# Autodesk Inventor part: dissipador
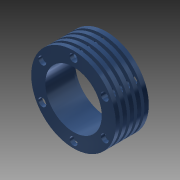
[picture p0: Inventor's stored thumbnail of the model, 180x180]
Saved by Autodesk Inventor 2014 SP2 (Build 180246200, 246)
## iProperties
Created: 2016-04
Part Number: dissipador
Material: Genérico
Document SubType Name: Modeling
Designer: Celiberto
Density: 1 g/cm^3
Appearance: Acetinada manchada - Azul
Mass: 2.14832 g
Surface Area: 38.898 cm^2
Volume: 2.14832 cm^3
Author: Celiberto
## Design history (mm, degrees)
sketch "Esboço1" dims "d10" = 10
  geometry: L1 (0, 0)-(16.385, 0); L2 (0, 0)-(0, 13.5); L3 (10.5, 13.5)-(10.5, 0); L4 (1.275, 13.5)-(1.275, 10.5); L5 (1.275, 10.5)-(2.275, 10.5); L6 (2.275, 10.5)-(2.275, 13.5); L7 (0, 13.5)-(1.275, 13.5); L8 (3.55, 13.5)-(3.55, 10.5); L9 (3.55, 10.5)-(4.55, 10.5); L10 (4.55, 10.5)-(4.55, 13.5); L11 (5.825, 13.5)-(5.825, 10.5); L12 (5.825, 10.5)-(6.825, 10.5); L13 (6.825, 10.5)-(6.825, 13.5); L14 (8.1, 13.5)-(8.1, 10.5); L15 (8.1, 10.5)-(9.1, 10.5); L16 (9.1, 10.5)-(9.1, 13.5); L17 (2.275, 13.5)-(3.55, 13.5); L18 (4.55, 13.5)-(5.825, 13.5); L19 (6.825, 13.5)-(8.1, 13.5); L20 (9.1, 13.5)-(10.5, 13.5)
  constraints: 40 end point, 8 perpendicular, 2 horizontal, 2 parallel, 1 point on line, 21 other
  dimensions: "d0" = 10.5 distance between parallel lines of L3 L2; "d2" = 1.275 distance between parallel lines of L2 L4; "d3" = 1 distance between parallel lines of L6 L4; "d4" = 21 diameter of L5 L1; "d7" = 2.275 distance of L4.start L8.start (= d2 + d3)
revolve "Revolução1" sketch "Esboço1" stored, may be unused: angle "d12" = 90 deg
sketch "Esboço2"
  geometry: C1 r 13.5 at (0, 0) reference; C2 r 9 at (0, 0)
  constraints: 1 centre point, 1 coincident
  dimensions: "d13" = 18 diameter of C2
extrude "Extrusão1" cut sketch "Esboço2" distance "d14" = 16.25; taper "d15" = 0 deg
sketch "Esboço3"
  geometry: C1 r 9 at (0, 0) reference; C2 r 13.5 at (0, 0) reference; C3 r 10 at (0, 0)
  constraints: 1 centre point, 1 coincident
  dimensions: "d16" = 20 diameter of C3
extrude "Extrusão2" cut sketch "Esboço3" distance "d17" = 1.5; taper "d18" = 0 deg
sketch "Esboço4" dims "d19" = 23
  geometry: C1 r 13.5 at (0, 0) reference; 2 further points
  constraints: 1 coincident, 1 vertical alignment, 2 other
hole "Furo1" sketch "Esboço4" at (0, 11.5) diameter "d20" = 2.5; stored, may be unused: countersink angle "d24" = 90 deg, drill point angle "d26" = 118 deg; dims "d21" = 6, "d22" = 4, "d23" = 2, "d25" = 8
pattern_circular "Padrão circular1" dims angle "d28" = 360 deg
node "Sólido1"
other parameters: "d1" = 27
